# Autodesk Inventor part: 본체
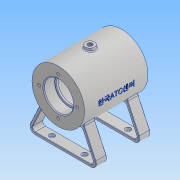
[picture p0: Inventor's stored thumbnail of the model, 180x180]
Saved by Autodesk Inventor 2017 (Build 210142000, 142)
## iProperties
Part Number: 본체
Material: 알루미늄 6061
Document SubType Name: Modeling
Designer: Administrator
Mass: 310.056 g
Surface Area: 355.353 cm^2
Volume: 114.836 cm^3
Density: 2.7 g/cm^3
Appearance: 알루미늄 - 평지
Author: Administrator
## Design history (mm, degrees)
sketch "스케치1"
  geometry: C1 r 29 at (0, 0); 1 further point
  constraints: 1 centre point, 1 coincident
  dimensions: "d0" = 58 diameter of C1
extrude "돌출1" new body sketch "스케치1" stored distance "d1" = 70; taper "d2" = 0 deg
node "작업 평면1"
sketch "스케치2"
  geometry: C1 r 5 at (0, 0); 1 further point
  constraints: 1 centre point, 1 coincident
  dimensions: "d4" = 10 diameter of C1
extrude "돌출2" join sketch "스케치2" stored distance "d5" = 70; taper "d6" = 0 deg
sketch "스케치3"
  geometry: C1 r 21 at (0, 0); 1 further point
  constraints: 1 centre point, 1 coincident
  dimensions: "d7" = 42 diameter of C1
extrude "돌출3" cut sketch "스케치3" stored distance "d8" = 42; taper "d9" = 0 deg
sketch "스케치4"
  geometry: C1 r 16 at (0, 0); 1 further point
  constraints: 1 centre point, 1 coincident
  dimensions: "d10" = 32 diameter of C1
extrude "돌출4" cut sketch "스케치4" distance "d11" = 12; taper "d12" = 0 deg
sketch "스케치5"
  geometry: C1 r 14 at (0, 0); 1 further point
  constraints: 1 centre point, 1 coincident
  dimensions: "d13" = 28 diameter of C1
extrude "돌출5" cut sketch "스케치5" stored distance "d14" = 12; taper "d15" = 0 deg
sketch "스케치6" dims "d16" = 42
  geometry: C1 r 16 at (0, 0) reference; C2 r 29 at (0, 0) reference; 3 further points
  constraints: 2 horizontal alignment, 1 coincident, 2 other
hole "구멍1" sketch "스케치6" at (21, 0) diameter "d17" = 3.242; stored, may be unused: countersink angle "d21" = 90 deg, drill point angle "d23" = 118 deg; dims "d18" = 8, "d19" = 4, "d20" = 2, "d22" = 10
sketch "스케치7"
  geometry: C1 r 1.5 at (0, 0); 1 further point
  constraints: 1 centre point, 1 coincident
  dimensions: "d27" = 3 diameter of C1
extrude "돌출6" cut sketch "스케치7" distance "d28" = 28.25; taper "d29" = 0 deg
sketch "스케치8"
  geometry: 1 further point
hole "구멍2" sketch "스케치8" at (0, 0) diameter "d30" = 5.188; stored, may be unused: countersink angle "d34" = 90 deg, drill point angle "d36" = 118 deg; dims "d31" = 6, "d32" = 4, "d33" = 2, "d35" = 8
node "작업 평면3"
  node "작업 평면2"
sketch "스케치9"
  geometry: C1 r 6 at (0, 0); 1 further point
  constraints: 1 centre point, 1 coincident
  dimensions: "d39" = 12 diameter of C1
extrude "돌출7" join sketch "스케치9" stored distance "d40" = 28.25; taper "d41" = 0 deg
sketch "스케치10"
  geometry: 1 further point
hole "구멍3" sketch "스케치10" at (0, 0) diameter "d42" = 5.188; stored, may be unused: countersink angle "d46" = 90 deg, drill point angle "d48" = 118 deg; dims "d43" = 6, "d44" = 4, "d45" = 2, "d47" = 24.5
node "작업 평면4"
sketch "스케치12"
  geometry: L1 (-22.743, -17.993)-(-40, -55); L2 (-40, -55)-(40, -55); L3 (40, -55)-(22.743, -17.993); L4 (20.024, -19.261)-(35.291, -52); L5 (35.291, -52)-(-35.291, -52); L6 (-35.291, -52)-(-20.024, -19.261); L7 (20.024, -19.261)-(22.743, -17.993); L8 (-22.743, -17.993)-(-20.024, -19.261); C1 r 1.621 at (0, 21) reference; C2 r 1.621 at (21, 0) reference; C3 r 1.621 at (0, -21) reference; C4 r 1.621 at (-21, 0) reference; C5 r 16 at (0, 0) reference; A1 r 29 centre (0, 0) between (-22.743, -17.993) and (22.743, -17.993) reference; 2 further points
  constraints: 16 end point, 2 perpendicular, 2 point on circle, 1 equal length, 1 horizontal, 1 midpoint, 1 vertical alignment, 2 other
  dimensions: "d60" = 80 distance of L1.end L2.end; "d61" = 55 distance from line of point (0, 0) L2; "d62" = 65 deg angle of L2 L1; "d63" = 3 distance between parallel lines of L3 L4
extrude "돌출8" join sketch "스케치12" distance "d64" = 12; taper "d65" = 0 deg
sketch "스케치13"
  geometry: L1 (80, 0)-(0, 0) reference; L2 (80, 0)-(80, 12) reference; L3 (0, 12)-(80, 12) reference; L4 (0, 0)-(0, 12) reference; C1 r 3 at (22, 6); C2 r 3 at (58, 6); 2 further points
  constraints: 2 centre point, 2 horizontal alignment, 1 midpoint
  dimensions: "d66" = 6 diameter of C1; "d67" = 6 diameter of C2; "d68" = 18 horizontal distance of point (40, 30) C1.centre; "d69" = 18 horizontal distance of point (40, 30) C2.centre
extrude "돌출9" cut sketch "스케치13" distance "d70" = 12; taper "d71" = 0 deg
fillet "모깎기1" dims "d72" = 6
fillet "모깎기2" dims "d73" = 6
fillet "모깎기3" dims "d74" = 3
fillet "모깎기4" dims "d75" = 3
fillet "모깎기5" dims "d76" = 0.3
fillet "모깎기6" dims "d77" = 0.3
chamfer "모따기1" distance "d78" = 1; stored, may be unused: second distance "d79" = 2, angle "d80" = 45 deg
fillet "모깎기7" dims "d81" = 3
fillet "모깎기8" dims "d82" = 0.5
node "작업 평면5"
sketch "스케치14"
  geometry: L1 (-29, -35)-(29, -35) reference; 2 further points
  constraints: 1 other
  dimensions: "d84" = 35 distance from line of point (0, 0) L1; "d85" = 29 horizontal distance of point (0, 0) L1.start
feature "엠보싱1" sketch "스케치14" dims "d86" = 0.5, "d87" = 0
fillet "모깎기9" dims "d88" = 1
node "솔리드1"
pattern_circular "원형 패턴1" dims angle "d25" = 360 deg
mirror "미러1"
mirror "미러2"
node "투영된 루프1"
node "투영된 루프2"
node "투영된 루프3"
other parameters: "d3" = 32, "d37" = 20 deg, "d38" = -32, "d49" = -5, "d83" = -73
